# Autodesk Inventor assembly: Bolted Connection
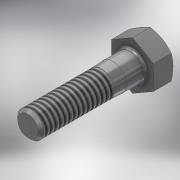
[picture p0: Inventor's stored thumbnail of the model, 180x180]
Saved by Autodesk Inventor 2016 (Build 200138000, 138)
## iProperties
ClientObjectVersion: 1
Created: 2016-01
Part Number: Bolted Connection
Document SubType Name: Assembly
Designer: Black Falcon
Author: Black Falcon
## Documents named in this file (2)
- E:\Learning Inventor\Belt Friction Apparatus\Final Assembly\Design Accelerator\Bolted Connection1.iam
- C:\Users\Black Falcon\Documents\Inventor\Content Center Files\R2016\en-US\ANSI ASME B18.2.1(2)\ANSI_ASME B18.2.1 - 5_16-18 UNC - 1.25(2).ipt
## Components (1 placed, 1 different names)
1. Hex Bolt - Inch 5/16-18 UNC - 1.25:1
